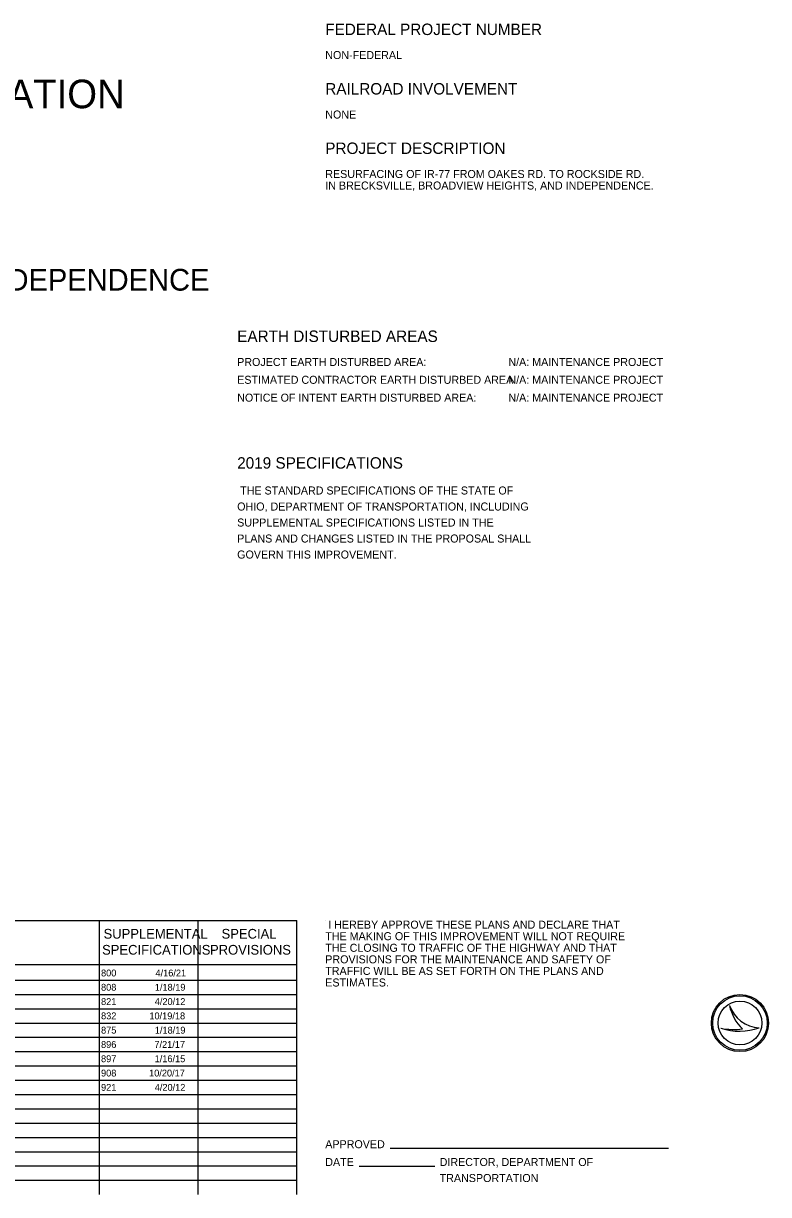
# Model space of a CAD drawing. Extents: x -17.5 to 72.9, y -57.8 to 32.3.
# Drawn here: x 19.67 to 32.7, y -47.95 to -27.46 of the extents above; entities that cross this region are included whole.
import ezdxf

# ---------------------------------------------------------------- set-up
doc = ezdxf.new("R2010")
doc.units = 0
doc.layers.add('Default', color=7, linetype='Continuous')
doc.layers.add('SH_Data', color=7, linetype='Continuous')

msp = doc.modelspace()

# ---------------------------------------------------------------- linework, layer by layer
at = {"layer": 'SH_Data'}
for p, q in [((10.995, -43.154), (24.445, -43.154)), ((20.995, -47.945), (20.995, -43.154)), ((22.72, -47.945), (22.72, -43.154)), ((24.445, -47.945), (24.445, -43.154)), ((24.945, -43.154), (24.945, -43.154)), ((10.995, -43.924), (24.445, -43.924)), ((10.995, -44.195), (24.445, -44.195)), ((10.995, -44.445), (24.445, -44.445)), ((32.013, -44.636), (32.013, -44.636)), ((10.995, -44.695), (24.445, -44.695)), ((10.995, -44.945), (24.445, -44.945)), ((31.862, -45.036), (31.862, -45.036)), ((32.533, -45.027), (32.533, -45.027)), ((10.995, -45.195), (24.445, -45.195)), ((10.995, -45.445), (24.445, -45.445)), ((10.995, -45.695), (24.445, -45.695)), ((10.995, -45.945), (24.445, -45.945)), ((10.995, -46.195), (24.445, -46.195)), ((10.995, -46.445), (24.445, -46.445)), ((10.995, -46.695), (24.445, -46.695)), ((10.995, -46.945), (24.445, -46.945)), ((10.995, -47.195), (24.445, -47.195)), ((26.08, -47.134), (30.945, -47.134)), ((10.995, -47.445), (24.445, -47.445)), ((25.536, -47.446), (26.859, -47.446)), ((10.995, -47.695), (24.445, -47.695))]:
    msp.add_line(p, q, dxfattribs=at)
for radius in [0.5, 0.477, 0.477, 0.382]:
    msp.add_circle((32.195, -44.945), radius, dxfattribs=at)
for centre, radius, start, end in [((32.561, -44.448), 0.58, 198.9257, 198.9319), ((32.792, -44.475), 0.796, 191.6379, 191.6421), ((32.561, -44.448), 0.58, 198.9319, 267.1657), ((32.792, -44.475), 0.796, 191.6421, 226.0947), ((32.093, -43.791), 1.266, 259.4964, 259.4995), ((32.185, -44.075), 1.013, 251.4527, 251.4576), ((32.185, -44.075), 1.013, 251.4576, 290.0832), ((32.093, -43.791), 1.266, 259.4995, 276.6672)]:
    msp.add_arc(centre, radius, start, end, dxfattribs=at)

# ---------------------------------------------------------------- texts
at = {"layer": 'Default'}
for s, height, p in [('FEDERAL PROJECT NUMBER', 0.2, (24.945, -27.665)), ('NON-FEDERAL', 0.14, (24.945, -28.085)), ('DEPARTMENT OF TRANSPORTATION', 0.5, (9.365, -28.945)), ('RAILROAD INVOLVEMENT', 0.2, (24.945, -28.705)), ('NONE', 0.14, (24.945, -29.125)), ('BRECKSVILLE, BROADVIEW HEIGHTS, INDEPENDENCE', 0.38, (9.338, -32.135)), ('DIRECTOR, DEPARTMENT OF', 0.14, (26.945, -47.446)), ('TRANSPORTATION', 0.14, (26.945, -47.726))]:
    msp.add_text(s, height=height, dxfattribs=at).set_placement(p)
at = {"layer": 'SH_Data'}
for s, height, p in [('PROJECT DESCRIPTION', 0.2, (24.945, -29.745)), ('RESURFACING OF IR-77 FROM OAKES RD. TO ROCKSIDE RD.', 0.14, (24.945, -30.165)), ('IN BRECKSVILLE, BROADVIEW HEIGHTS, AND INDEPENDENCE.', 0.14, (24.945, -30.367)), ('EARTH DISTURBED AREAS', 0.2, (23.405, -33.033)), ('PROJECT EARTH DISTURBED AREA:', 0.14, (23.405, -33.453)), ('N/A: MAINTENANCE PROJECT', 0.14, (28.147, -33.453)), ('ESTIMATED CONTRACTOR EARTH DISTURBED AREA:', 0.14, (23.405, -33.765)), ('N/A: MAINTENANCE PROJECT', 0.14, (28.147, -33.765)), ('NOTICE OF INTENT EARTH DISTURBED AREA:', 0.14, (23.405, -34.077)), ('N/A: MAINTENANCE PROJECT', 0.14, (28.147, -34.077)), ('2019 SPECIFICATIONS', 0.2, (23.405, -35.249)), (' THE STANDARD SPECIFICATIONS OF THE STATE OF', 0.14, (23.405, -35.701)), ('OHIO, DEPARTMENT OF TRANSPORTATION, INCLUDING', 0.14, (23.405, -35.981)), ('SUPPLEMENTAL SPECIFICATIONS LISTED IN THE', 0.14, (23.405, -36.261)), ('PLANS AND CHANGES LISTED IN THE PROPOSAL SHALL', 0.14, (23.405, -36.541)), ('GOVERN THIS IMPROVEMENT.', 0.14, (23.405, -36.821)), (' I HEREBY APPROVE THESE PLANS AND DECLARE THAT', 0.14, (24.945, -43.294)), ('SUPPLEMENTAL', 0.17, (21.069, -43.469)), ('SPECIAL', 0.17, (23.132, -43.469)), ('THE MAKING OF THIS IMPROVEMENT WILL NOT REQUIRE', 0.14, (24.945, -43.496)), ('SPECIFICATIONS', 0.17, (21.043, -43.749)), ('PROVISIONS', 0.17, (22.93, -43.749)), ('THE CLOSING TO TRAFFIC OF THE HIGHWAY AND THAT', 0.14, (24.945, -43.699)), ('PROVISIONS FOR THE MAINTENANCE AND SAFETY OF', 0.14, (24.945, -43.901)), ('800', 0.12, (21.025, -44.13)), ('4/16/21', 0.12, (21.977, -44.13)), ('TRAFFIC WILL BE AS SET FORTH ON THE PLANS AND', 0.14, (24.945, -44.104)), ('ESTIMATES.', 0.14, (24.945, -44.306)), ('808', 0.12, (21.025, -44.38)), ('1/18/19', 0.12, (21.965, -44.38)), ('821', 0.12, (21.025, -44.63)), ('4/20/12', 0.12, (21.964, -44.63)), ('832', 0.12, (21.025, -44.88)), ('10/19/18', 0.12, (21.87, -44.88)), ('875', 0.12, (21.025, -45.13)), ('1/18/19', 0.12, (21.965, -45.13)), ('896', 0.12, (21.025, -45.38)), ('7/21/17', 0.12, (21.958, -45.38)), ('897', 0.12, (21.025, -45.63)), ('1/16/15', 0.12, (21.962, -45.63)), ('908', 0.12, (21.025, -45.88)), ('10/20/17', 0.12, (21.865, -45.88)), ('921', 0.12, (21.025, -46.13)), ('4/20/12', 0.12, (21.964, -46.13)), ('APPROVED', 0.14, (24.945, -47.134)), ('DATE', 0.14, (24.945, -47.446))]:
    msp.add_text(s, height=height, dxfattribs=at).set_placement(p)

doc.saveas('drawing.dxf')
